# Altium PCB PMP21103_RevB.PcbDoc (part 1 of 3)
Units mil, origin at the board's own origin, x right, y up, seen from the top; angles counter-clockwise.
Board outline 3500 x 4000 mil, 4 copper layers (Top Layer, Signal Layer 1, Signal Layer 2, Bottom Layer), stack 61.2 mil thick; 194 components, 123 nets, 630 pads, 189 vias.
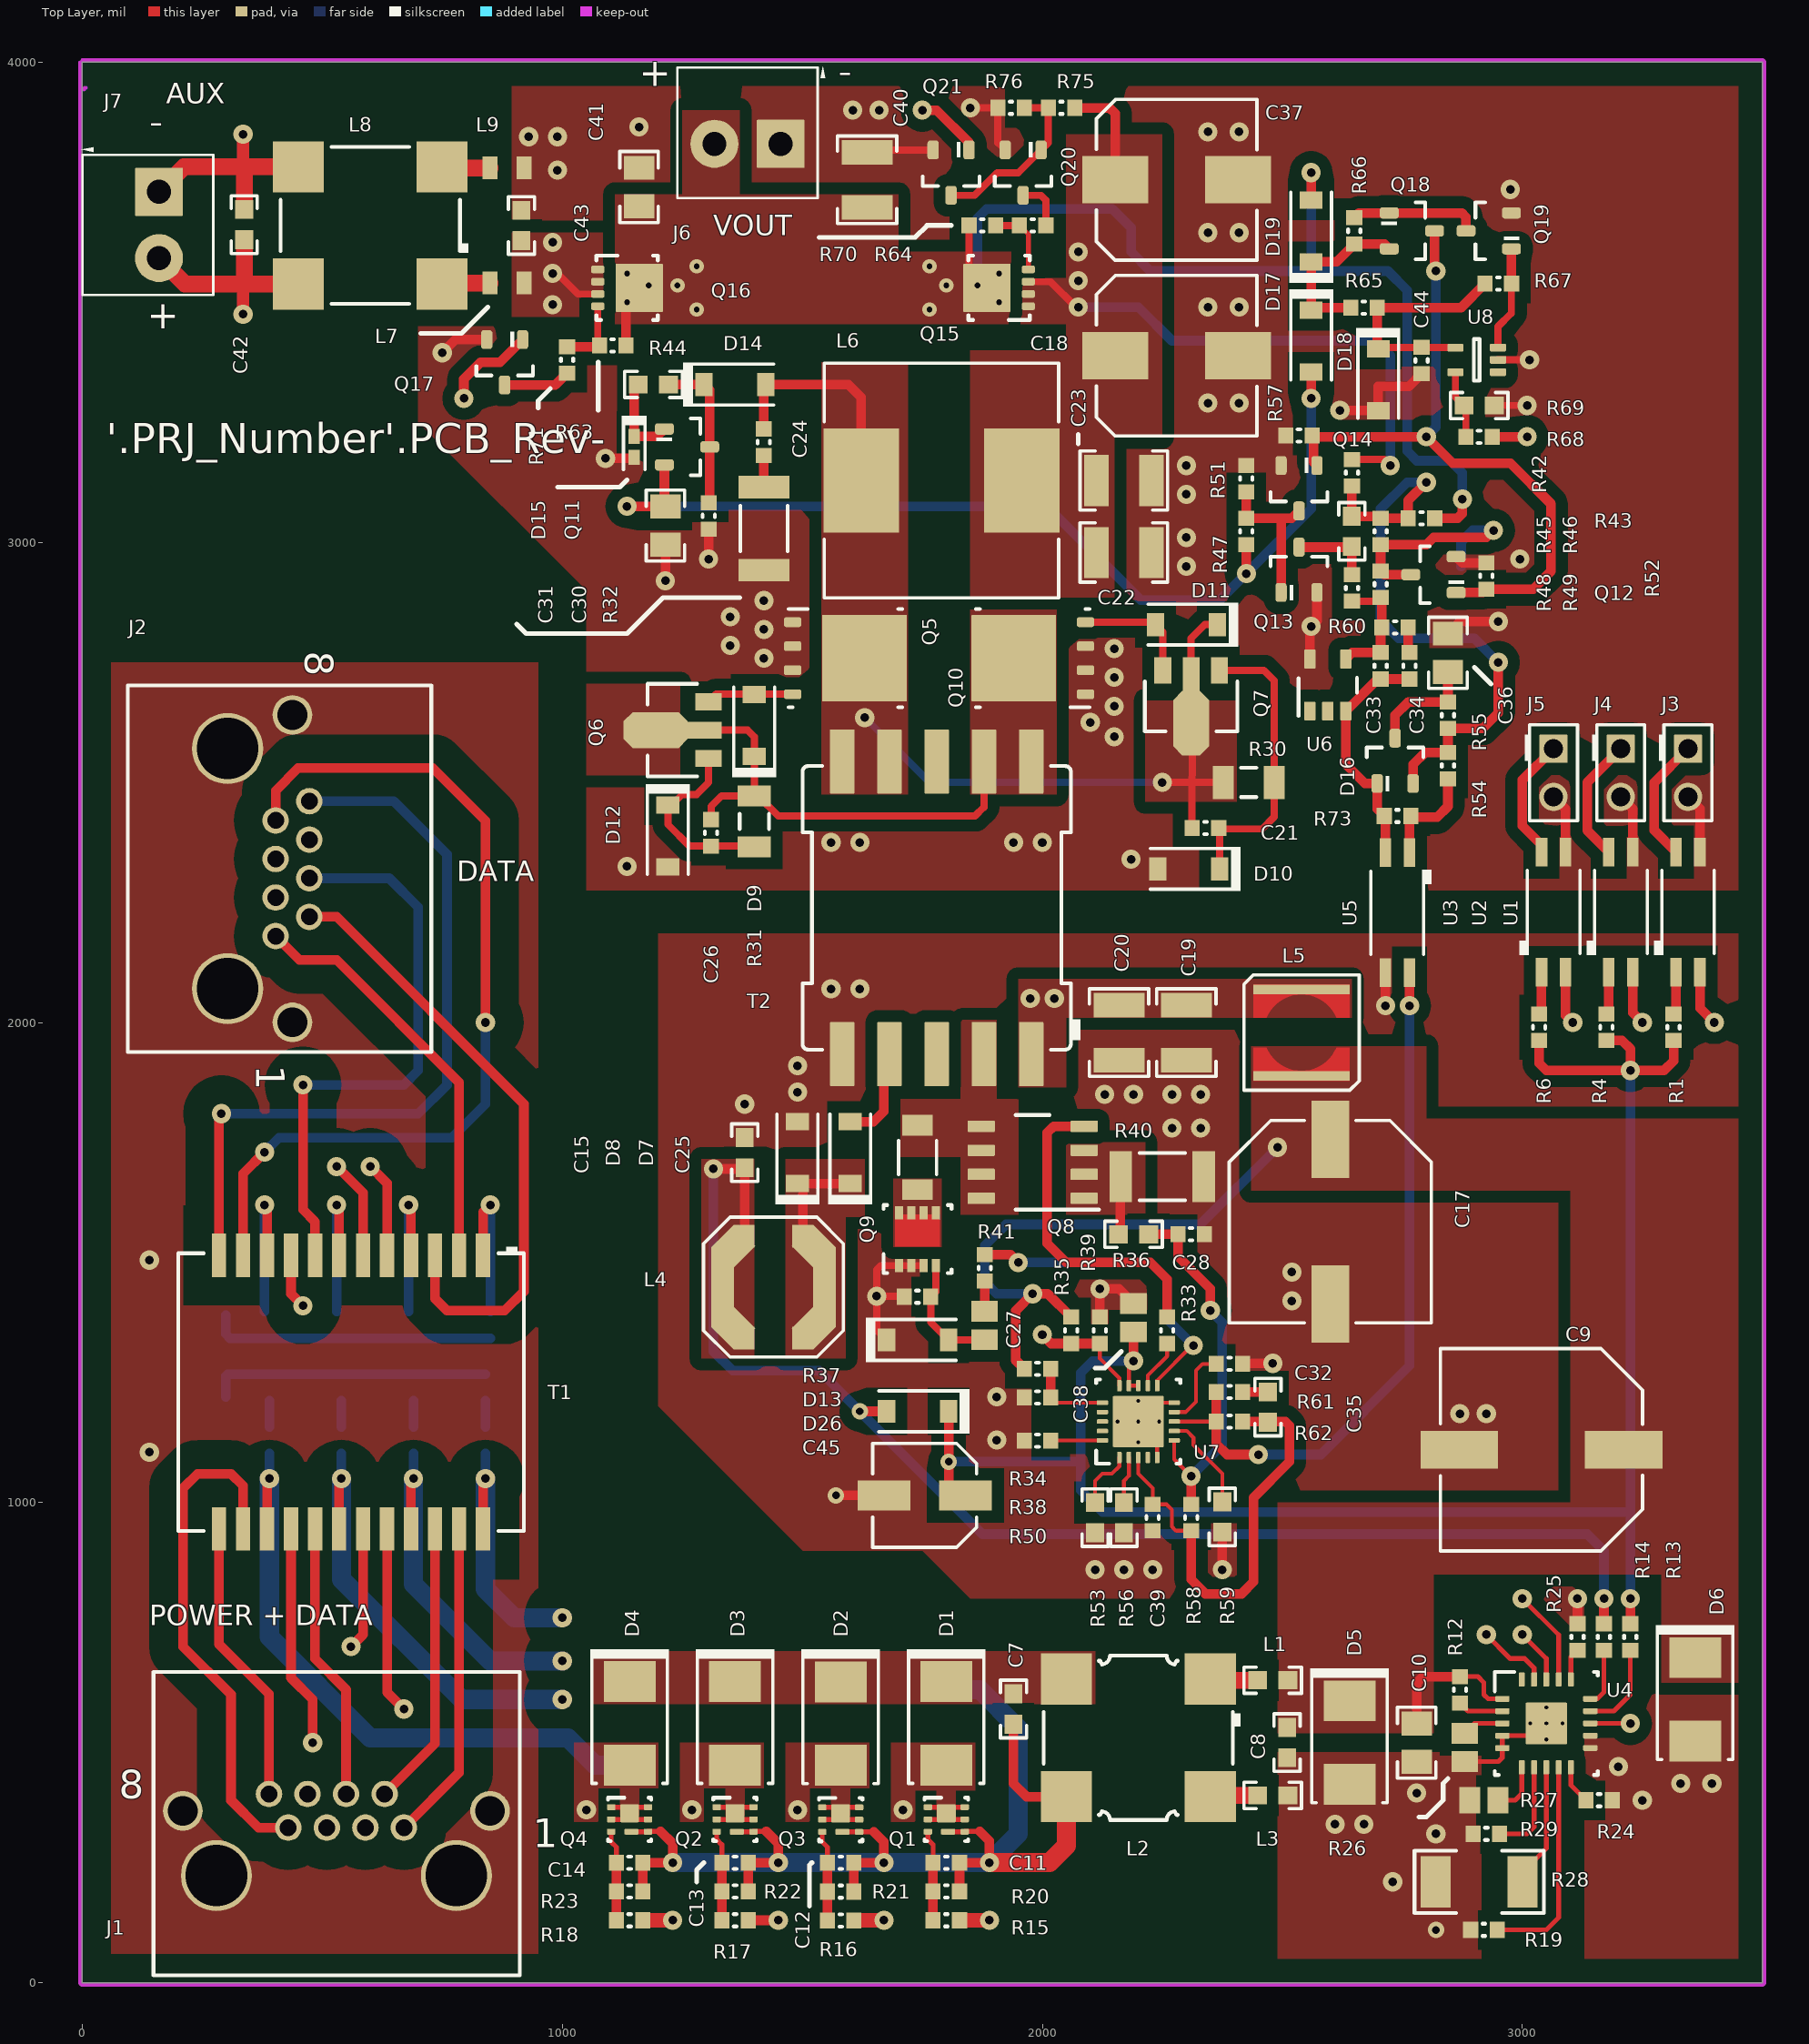
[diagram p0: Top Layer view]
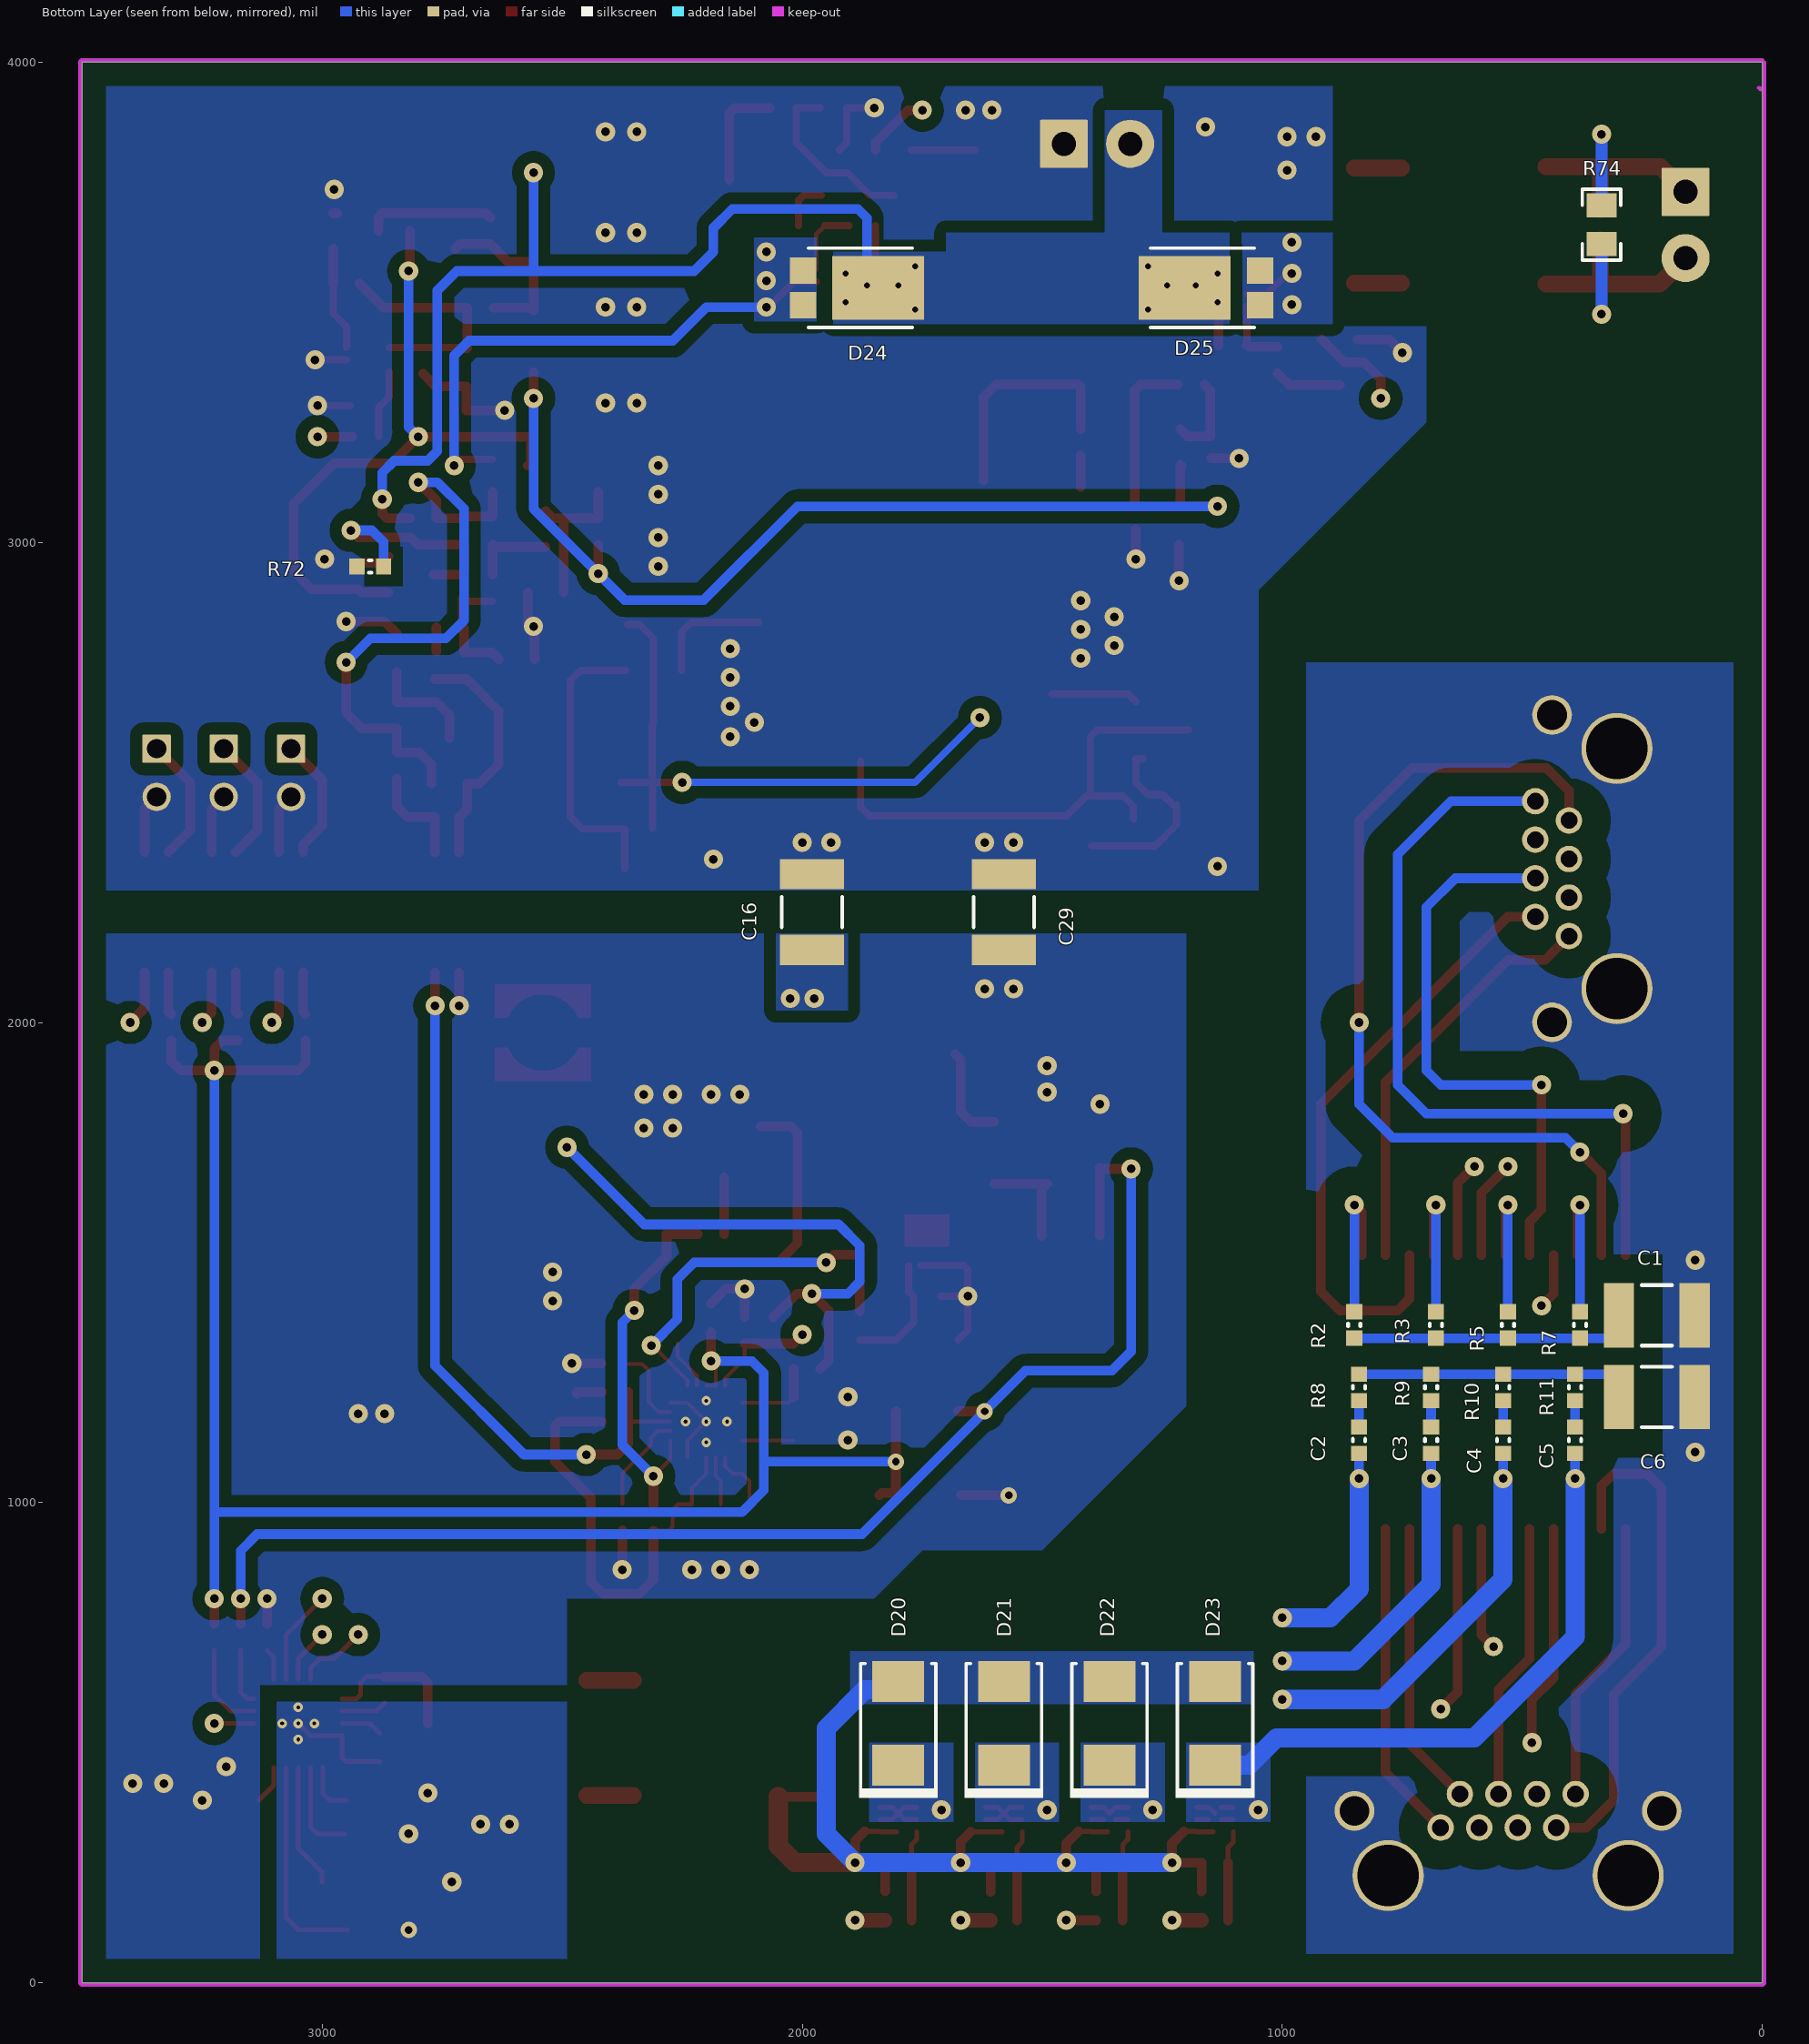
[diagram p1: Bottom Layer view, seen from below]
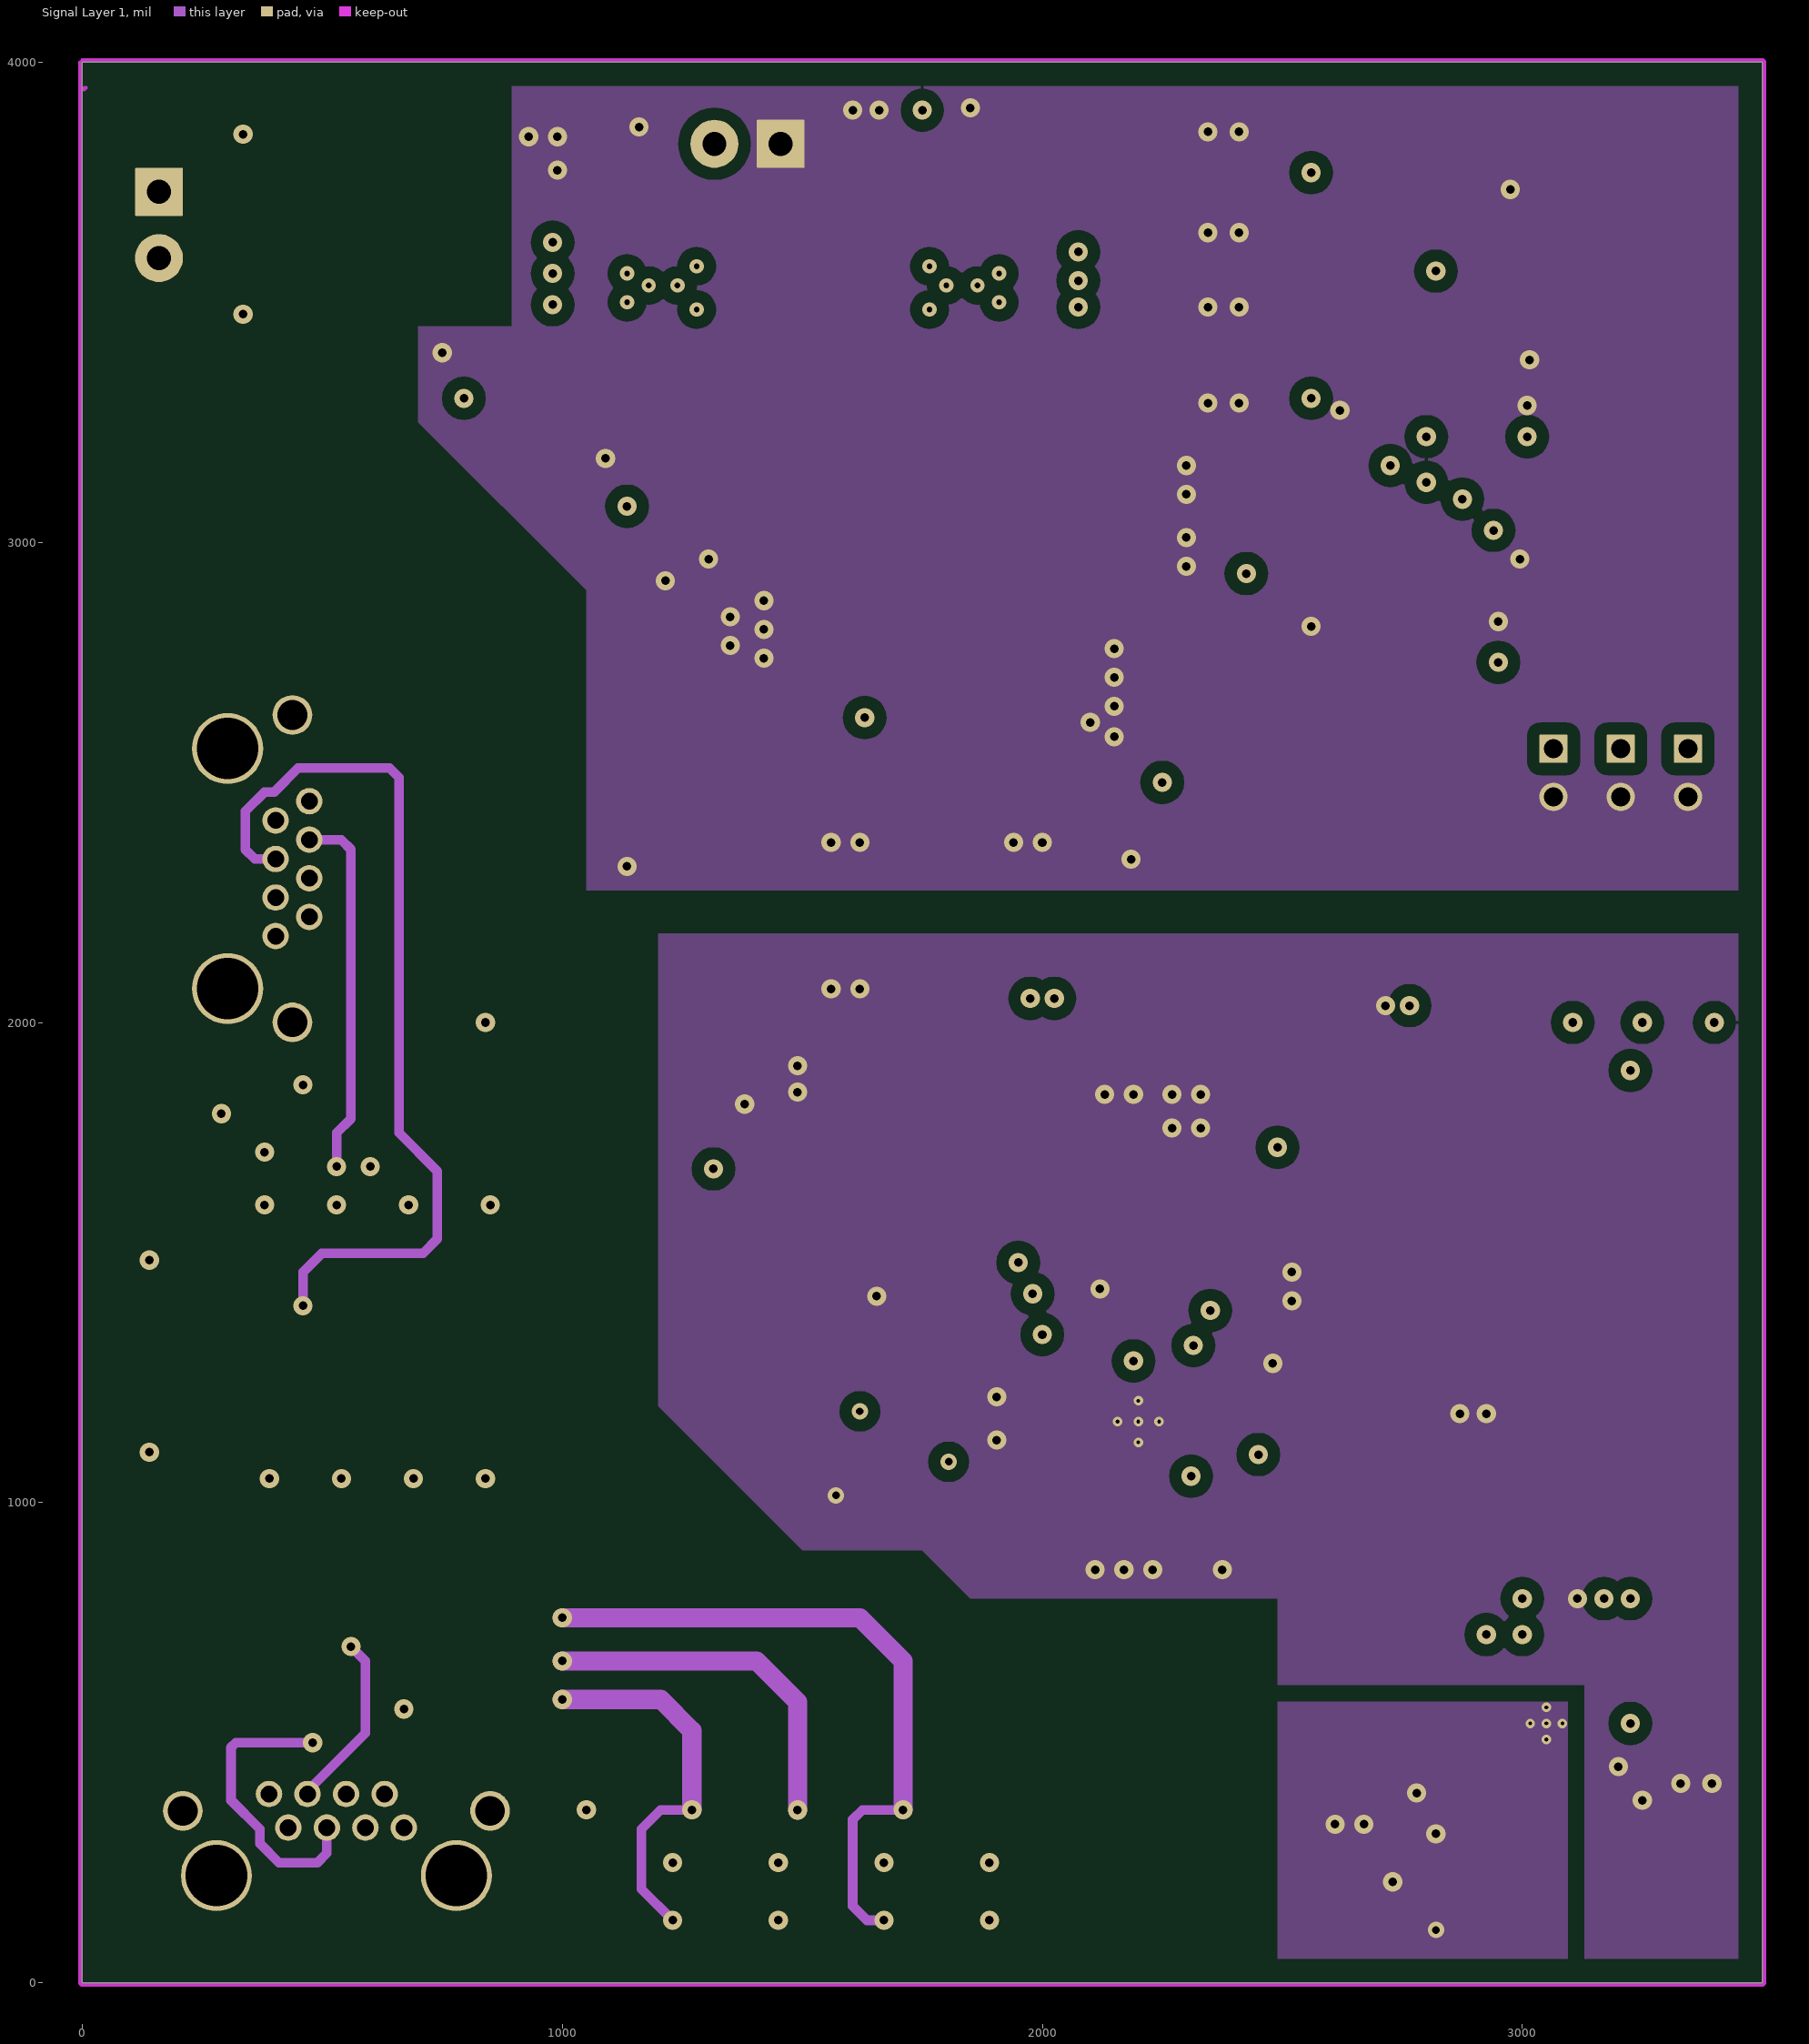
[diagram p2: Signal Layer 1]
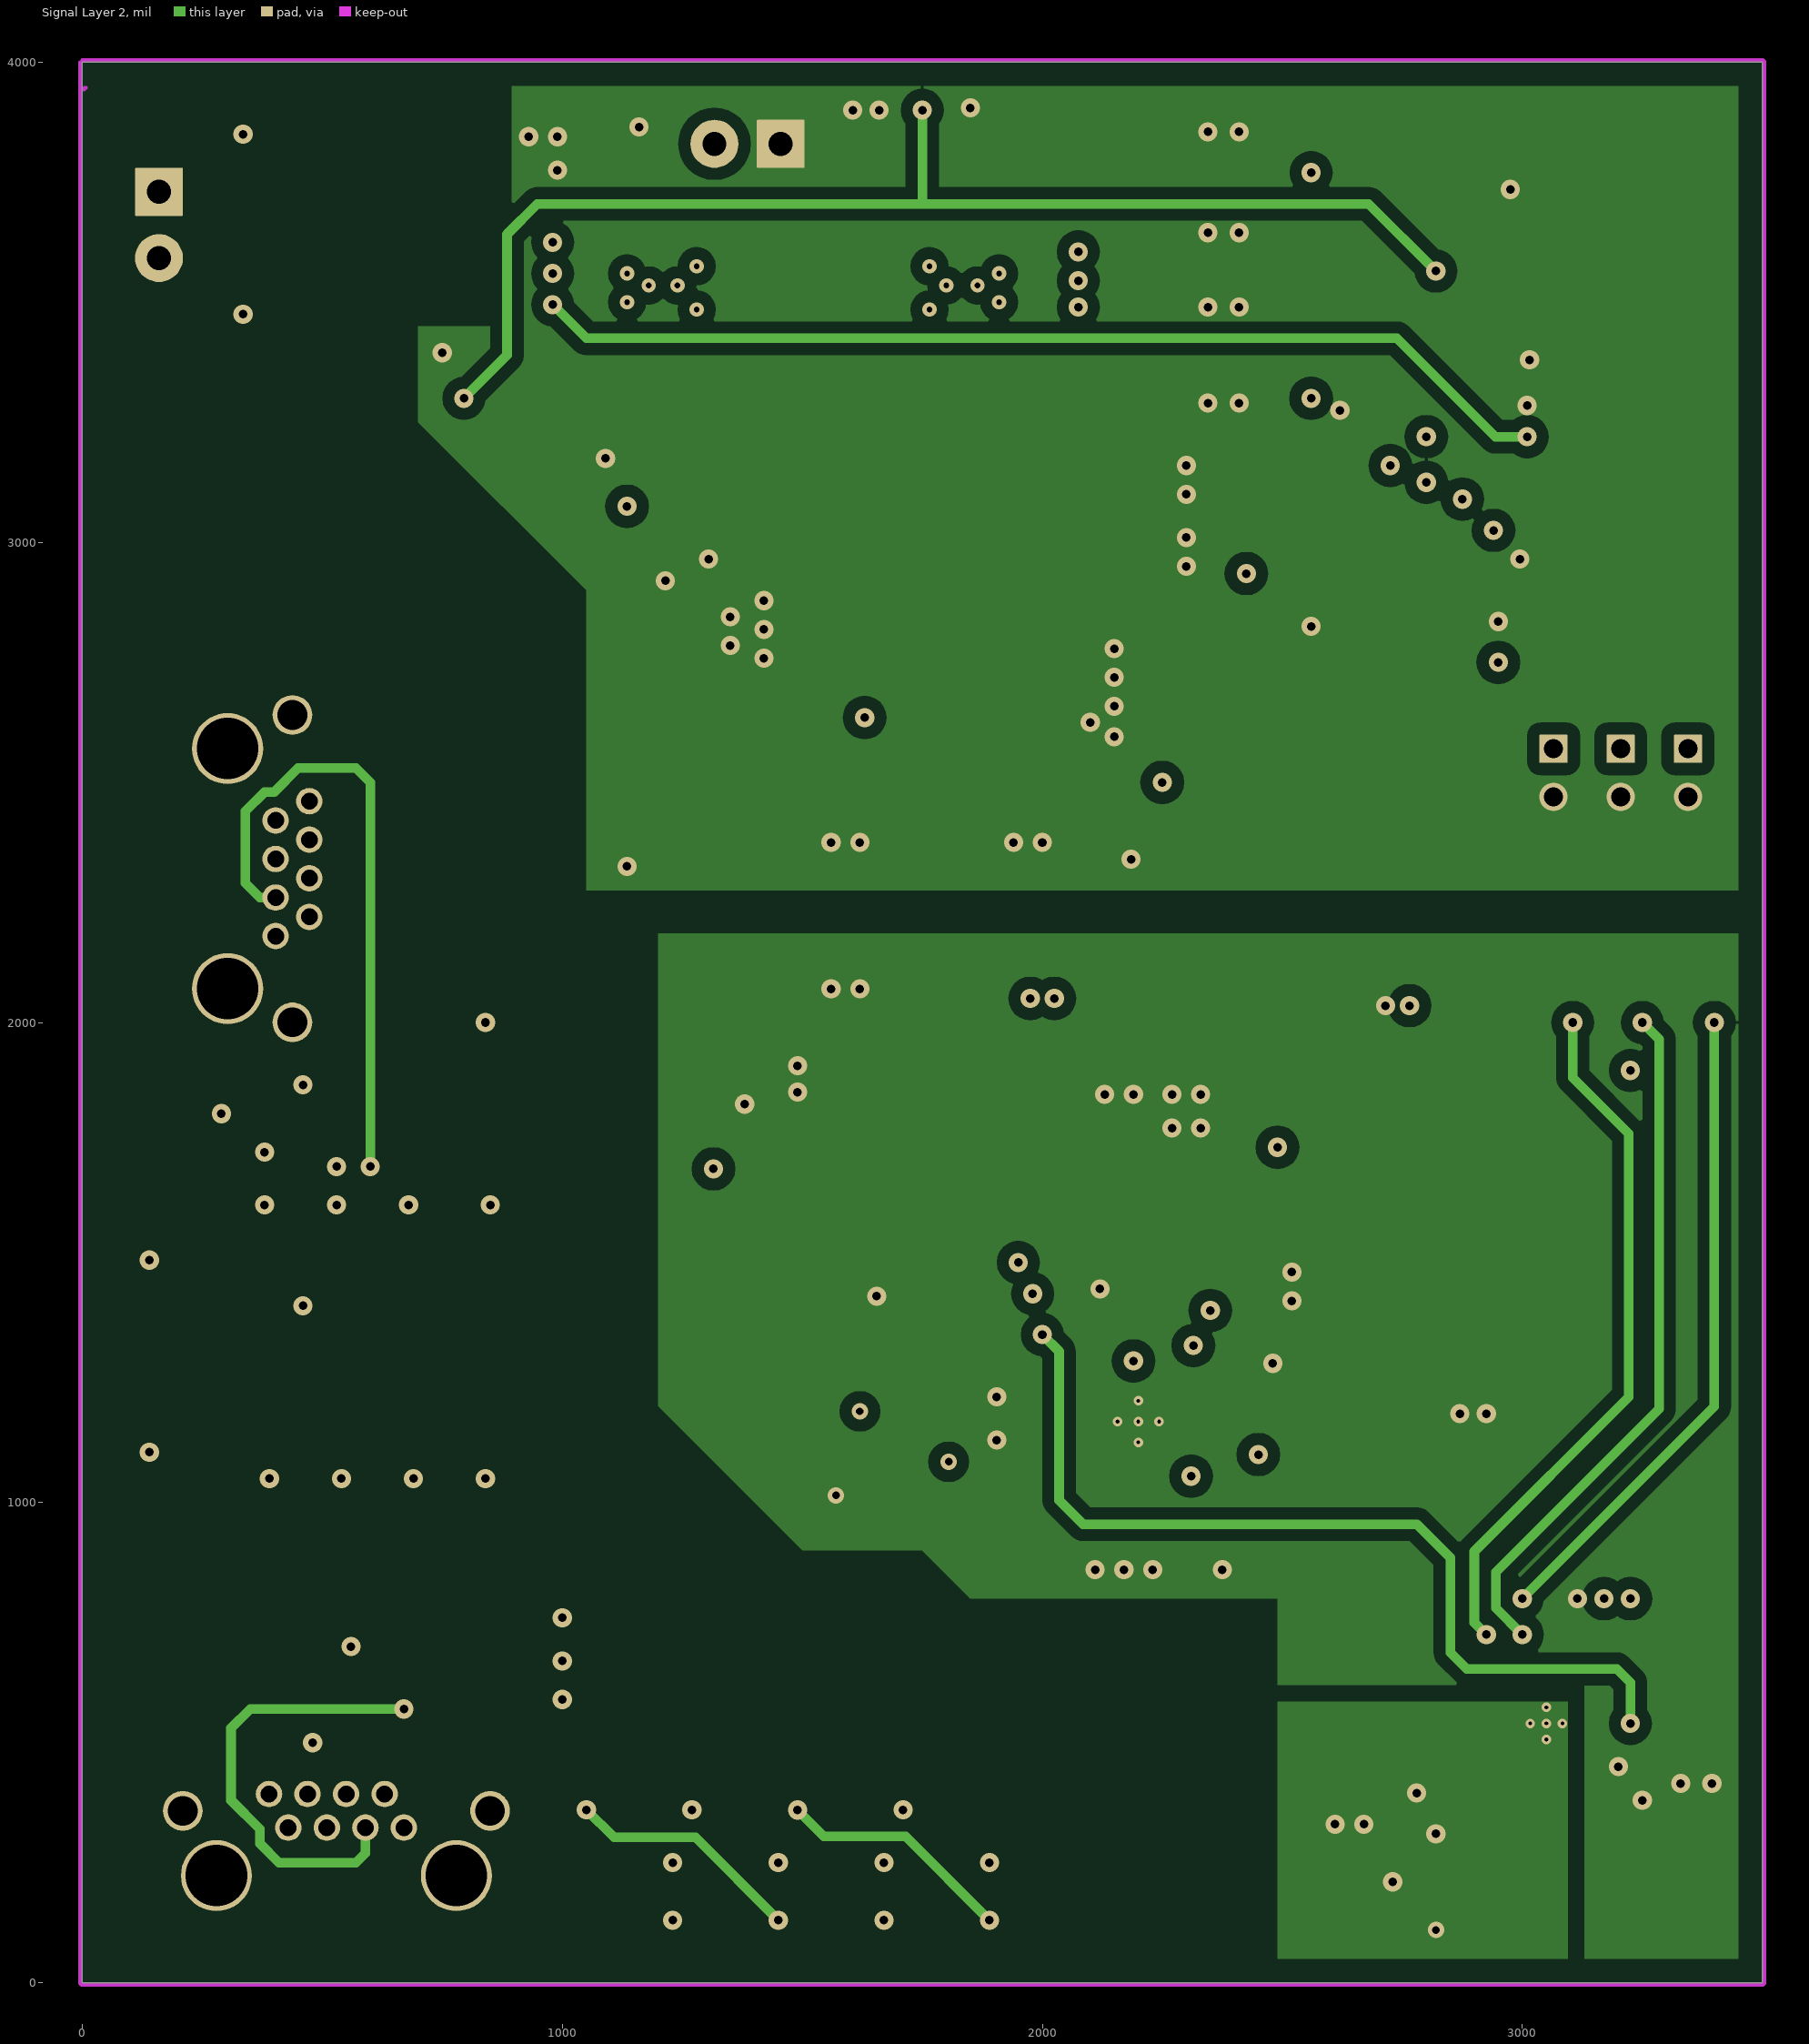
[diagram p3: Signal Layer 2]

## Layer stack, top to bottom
Top Solder: solder mask 0.4, Solder Resist, Dk 3.5
Top Layer: signal copper 2.8
Dielectric 2: core 20, Dk 4.2
Signal Layer 1: signal copper 2.8
Dielectric1: prepreg 10, FR-4, Dk 4.2
Signal Layer 2: signal copper 2.8
Dielectric 3: core 20, Dk 4.2
Bottom Layer: signal copper 2.8
Bottom Solder: solder mask 0.4, Solder Resist, Dk 3.5

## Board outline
0,0 3500,0 3500,4000 0,4000

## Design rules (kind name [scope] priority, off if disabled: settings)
AcuteAngle [All] p1: minimum=4.50000000000000E+0001 checktracksonly=FALSE
AssemblyTestPointUsage [All] p1: valid=2
BoardOutlineClearance BoardOutlineClearance_MountingHoles [OnCopper and InComponentClass('Mounting Holes')] p1: gap=40 ignorepadtopadclearanceinfootprint=FALSE
BoardOutlineClearance BoardOutlineClearance_Poly [OnCopper and IsPoly] p2: gap=25 ignorepadtopadclearanceinfootprint=FALSE
BoardOutlineClearance [OnCopper and Not InComponentClass('Logo') and not InComponentClass('FiducialMark') and not InRegion(1000,500,4000,800) and not InPoly] p3: gap=75 ignorepadtopadclearanceinfootprint=FALSE
Clearance Clearance_2 [InNamedPolygon('TOP_LAYER_BSVG_P132')] p1: gap=60 ignorepadtopadclearanceinfootprint=FALSE
Clearance Clearance_1 [InNamedPolygon('BOTTOM_LAYER_BSVG_P134')] p2: gap=60 ignorepadtopadclearanceinfootprint=FALSE
Clearance Clearance_Keepouts [((IsTrack Or IsArc) And Not InPoly) And IsFree and IsKeepOut vs ((IsTrack Or IsArc) And Not InPoly) And IsFree and IsKeepOut] p3: gap=0 ignorepadtopadclearanceinfootprint=FALSE
Clearance Clearance_Poly [InPolygon] p4: gap=25 ignorepadtopadclearanceinfootprint=FALSE except(0: Arc-Hole Track-Hole SMDPad-Hole THPad-Hole Via-Hole Fill-Hole Poly-Hole Region-Hole Text-Hole)
Clearance Clearance_FiducialMark [IsKeepOut and InComponentClass('FiducialMark') vs IsPad and InComponentClass('FiducialMark')] p5: gap=0 ignorepadtopadclearanceinfootprint=FALSE
Clearance [All] p6: gap=7.87 ignorepadtopadclearanceinfootprint=FALSE except(0: Arc-Hole Track-Hole SMDPad-Hole THPad-Hole Via-Hole Fill-Hole Poly-Hole Region-Hole Text-Hole)
ComponentClearance ComponentClearance_MountingHoles_FiducialMarks [InComponentClass('Mounting Holes') vs InComponentClass('FiducialMark')] p1: gap=50 collisioncheckmode=3 verticalgap=10 showdistances=FALSE
ComponentClearance ComponentClearance_Shunt [InComponentClass('Header') vs InComponentClass('Shunt')] p2: gap=0 collisioncheckmode=3 verticalgap=0 showdistances=FALSE
ComponentClearance ComponentClearance_Logo [InComponentClass('Logo')] p3: gap=50 collisioncheckmode=3 verticalgap=10 showdistances=FALSE
ComponentClearance ComponentClearance_ScrewToNut [(HasFootprint('NY PMS 440 0025 PH')) vs (HasFootprint('Keystone_1902C'))] p4: gap=5 collisioncheckmode=3 verticalgap=10 showdistances=FALSE
ComponentClearance ComponentClearance_MountingHoles [InComponentClass('Mounting Holes')] p5: gap=250 collisioncheckmode=3 verticalgap=100000 showdistances=FALSE
ComponentClearance ComponentClearance_SmallPassives [HasFootprint('0201*') or HasFootprint('0402*') or HasFootprint('0508') or HasFootprint('0603*') or HasFootprint('0612') or HasFootprint('0805*') or HasFootprint('0815*') or HasFootprint('0830*') or HasFootprint('1206*') or HasFootprint('1210*') or HasFootprint('1808*') or HasFootprint('1812*') or HasFootprint('1825*') or HasFootprint('2010*') or HasFootprint('2220*') or HasFootprint('2225*') or HasFootprint('2512*') or HasFootprint('2728*') or HasFootprint('3518*') vs HasFootprint('0201*') or HasFootprint('0402*') or HasFootprint('0508') or HasFootprint('0603*') or HasFootprint('0612') or HasFootprint('0805*') or HasFootprint('0815*') or HasFootprint('0830*') or HasFootprint('1206*') or HasFootprint('1210*') or HasFootprint('1808*') or HasFootprint('1812*') or HasFootprint('1825*') or HasFootprint('2010*') or HasFootprint('2220*') or HasFootprint('2225*') or HasFootprint('2512*') or HasFootprint('2728*') or HasFootprint('3518*')] p6: gap=14.96 collisioncheckmode=3 verticalgap=10 showdistances=FALSE
ComponentClearance ComponentClearance_THtoSMT [IsThruComponent vs IsSMTComponent] p7: gap=40 collisioncheckmode=3 verticalgap=30 showdistances=FALSE
ComponentClearance ComponentClearance_THtoTH [IsThruComponent vs IsThruComponent] p8: gap=30 collisioncheckmode=3 verticalgap=30 showdistances=FALSE
ComponentClearance [All] p9: gap=30 collisioncheckmode=3 verticalgap=10 showdistances=FALSE
DiffPairsRouting [All] p1: maxlimit=100 minlimit=10 mostfreqgap=10 toplayer_minwidth=15 toplayer_maxwidth=15 toplayer_prefwidth=15 midlayer1_minwidth=15 midlayer1_maxwidth=15 midlayer1_prefwidth=15 midlayer2_minwidth=15 midlayer2_maxwidth=15 midlayer2_prefwidth=15 bottomlayer_minwidth=15 bottomlayer_maxwidth=15 bottomlayer_prefwidth=15 maxuncoupledlength=1000
FabricationTestPointUsage TestPointUsage [All] p1: valid=2 allowmultiple=FALSE
FabricationTestpoint Testpoint [All] p1: side=3 testpointundercomponent=TRUE minsize=40 maxsize=100 preferedsize=60 minholesize=0 maxholesize=40 preferedholesize=32 testpointgrid=1 allowsidetop=TRUE allowsidebottom=TRUE usegrid=TRUE gridtolerance=0.01
FanoutControl Fanout_LCC [IsLCC] p1: bgadir=Out bgaviamode=Centered fanoutstyle=Auto fanoutdirection=Alternating viagrid=1 // Fanout_LCC (Default Rule)
FanoutControl Fanout_BGA [IsBGA] p2: bgadir=Out bgaviamode=Centered fanoutstyle=Auto fanoutdirection=Alternating viagrid=1 // Fanout_BGA (Default Rule)
FanoutControl Fanout_Default [All] p4: bgadir=Out bgaviamode=Centered fanoutstyle=Auto fanoutdirection=Alternating viagrid=1 // Fanout_Default (Default Rule)
FanoutControl Fanout_Small [(CompPinCount < 5)] p5: bgadir=Out bgaviamode=Centered fanoutstyle=Auto fanoutdirection=OutThenIn viagrid=1 // Fanout_Small (Default Rule)
HoleSize [All] p1: absolutevalues=TRUE maxlimit=251 minlimit=7.87 maxpercent=80.000 minpercent=20.000
MinimumAnnularRing MinimumAnnularRing_ThermalPadVias [IsVia and InAnyComponent] p1: minimumring=5.91
MinimumAnnularRing [All] p2: minimumring=8
MinimumSolderMaskSliver MinimumSolderMaskSliver_Logo [InComponentClass('Logo') vs InComponentClass('Logo')] p1: minsoldermaskwidth=0.7
MinimumSolderMaskSliver [All] p2: minsoldermaskwidth=3.94
PlaneConnect [All] p1: planeconnectstyle=Relief reliefexpansion=10 reliefentries=4 reliefconductorwidth=10 reliefairgap=10
PolygonConnect [All] p1: connectstyle=Direct reliefconductorwidth=10 reliefentries=4 polygonreliefangle="90 Angle" airgapwidth=10
RoutingVias ThermalPadVias [IsVia and InAnyComponent] p1: holewidth=7.87 width=19.68 viastyle="Through Hole" minholewidth=7.87 minwidth=19.68 maxholewidth=12.99 maxwidth=23.62
RoutingVias [All] p2: holewidth=18 width=40 viastyle="Through Hole" minholewidth=7.87 minwidth=26 maxholewidth=40 maxwidth=65
SilkToBoardRegionClearance [Not ((IsComment or IsDesignator) And (Hide <> 'False')) and not InRegion(1000,500,4000,800)] p1:
SilkToSilkClearance SilkToSilkClearance_Pb-FreeLogo [(HasFootprint('Pb-Free_Overlay_Medium') OR HasFootprint('Pb-Free_Overlay_Small')) vs (HasFootprint('Pb-Free_Overlay_Medium') OR HasFootprint('Pb-Free_Overlay_Small'))] p1: silktosilkclearance=0
SilkToSilkClearance [All] p2: silktosilkclearance=4
SilkToSolderMaskClearance SilkToComponentPadClearance [(IsPad or IsFill or IsRegion) and InAnycomponent] p1: minsilkscreentomaskgap=5 clearancetoexposedcopper=TRUE
SilkToSolderMaskClearance "Silk to Solder Mask Opening" [All] p2: minsilkscreentomaskgap=4 clearancetoexposedcopper=FALSE
SolderMaskExpansion [All] p1: expansion=1.97
Width [All] p1: maxlimit=100 minlimit=6 preferedwidth=10 checkconnectedcopper=TRUE
15 further rules are at their usual default settings.

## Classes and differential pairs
component class Header: J3 J4 J5
component class PMP21103_RevB_SH1: C1 C2 C3 C4 C5 C6 C7 C8 C9 C10 C11 C12 C13 C14 D1 D2 D3 D4 D5 D6 D20 D21 D22 D23 D26 J1 J2 J3 J4 J5 L1 L2 L3 Q1 Q2 Q3 Q4 R1 R2 R3 R4 R5 R6 R7 R8 R9 R10 R11 R12 R13 R14 R15 R16 R17 R18 R19 R20 R21 R22 R23 R24 R25 R26 R27 R28 R29 T1 U1 U2 U3 U4
component class PMP21103_RevB_SH2: C15 C16 C17 C18 C19 C20 C21 C22 C23 C24 C25 C26 C27 C28 C29 C30 C31 C32 C33 C34 C35 C36 C37 C38 C39 C45 D7 D8 D9 D10 D11 D12 D13 D14 D15 D16 L4 L5 L6 Q5 Q6 Q7 Q8 Q9 Q10 Q11 Q12 Q13 Q14 R30 R31 R32 R33 R34 R35 R36 R37 R38 R39 R40 R41 R42 R43 R44 R45 R46 R47 R48 R49 R50 R51 R52 R53 R54 R55 R56 R57 R58 R59 R60 R61 R62 R72 R73 T2 U5 U6 U7
component class PMP21103_RevB_SH3: C40 C41 C42 C43 C44 D17 D18 D19 D24 D25 J6 J7 L7 L8 L9 Q15 Q16 Q17 Q18 Q19 Q20 Q21 R63 R64 R65 R66 R67 R68 R69 R70 R71 R74 R75 R76 U8

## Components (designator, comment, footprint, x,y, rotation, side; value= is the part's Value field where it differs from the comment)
C1 "GR443QR73D102KW01L" 1812 220,1390 r0 bottom value=1000pF
C2 "GRM188R72A103KA01D" 0603L 840,1130 r90 bottom value=0.01uF
C3 "GRM188R72A103KA01D" 0603L 690,1130 r90 bottom value=0.01uF
C4 "GRM188R72A103KA01D" 0603L 540,1130 r90 bottom value=0.01uF
C5 "GRM188R72A103KA01D" 0603L 390,1130 r90 bottom value=0.01uF
C6 "GR443QR73D102KW01L" 1812 220,1220 r180 bottom value=1000pF
C7 "GRM188R72A102KA01D" 0603 1940,570 r270 top value=1000pF
C8 "GRM188R72A102KA01D" 0603 2510,500 r270 top value=1000pF
C9 "EEE-FK1K470P" SM_RADIAL_G 3040,1110 r180 top value=47uF
C10 "C2012X7R2A104K125AA" 0805_HV 2780,500 r90 top value=0.1uF
C11 "GRM1885C1H331JA01D" 0603L 1800,250 r0 top value=330pF
C12 "GRM1885C1H331JA01D" 0603L 1580,249.69 r0 top value=330pF
C13 "GRM1885C1H331JA01D" 0603L 1360,250 r0 top value=330pF
C14 "GRM1885C1H331JA01D" 0603L 1140.32,250 r0 top value=330pF
C15 "C1608X7R1H104K080AA" 0603 1380,1728.74 r270 top value=0.1uF
C16 "C4532X7R3D222K130KA" 1812 1980,2230 r270 bottom value=2200pF
C17 "EEE-FK1K470P" SM_RADIAL_G 2600,1585 r270 top value=47uF
C18 "20SVP47M" SM_RADIAL_8MM 2280,3388.74 r0 top value=47uF
C19 "GRM32ER72A225KA35L" 1210_270 2300,1978.74 r270 top value=2.2uF
C20 "GRM32ER72A225KA35L" 1210_270 2160,1978.74 r270 top value=2.2uF
C21 "C1608C0G1H101J080AE" 0603L 2340,2405 r180 top value=100pF
C22 "885012209028" 1210_220 2170,2978.74 r0 top value=10uF
C23 "885012209028" 1210_220 2170,3128.74 r0 top value=10uF
C24 "GRM188R71H222KA01D" 0603L 1420,3208.74 r270 top value=2200pF
C25 "GRM31CR72E473KW03L" 1206_180 1740,1718.74 r270 top value=0.047uF
C26 "C1608C0G1H101J080AE" 0603L 1310,2395 r270 top value=100pF
C27 "GRM21BR71E105KA99L" 0805L 1880,1368.74 r90 top value=1uF
C28 "GRM1885C1H470JA01D" 0603L 2310,1558.74 r0 top value=47pF
C29 "C4532X7R3D222K130KA" 1812 1580,2230 r270 bottom value=2200pF
C30 "C1608X7R1H104K080AA" 0603L 1305,3055 r90 top value=0.1uF
C31 "GRM21BR71E105KA99L" 0805_HV 1215,3035 r270 top value=1uF
C32 "GRM188R71H223KA01D" 0603L 2390,1288.74 r0 top value=0.022uF
C33 "C1608C0G1H101J080AE" 0603L 2704.8,2742.77 r270 top value=100pF
C34 "GRM188R71H223KA01D" 0603L 2764.8,2742.77 r270 top value=0.022uF
C35 "GRM188R71H102KA01D" 0603 2470,1198.74 r270 top value=1000pF
C36 "GRM21BR71E105KA99L" 0805_HV 2845,2770 r90 top value=1uF
C37 "20SVP47M" SM_RADIAL_8MM 2280,3755 r0 top value=47uF
C38 "GRM21BR71E105KA99L" 0805L 2190,1385 r90 top value=1uF
C39 "C1608X7R1H104K080AA" 0603L 2230,968.74 r90 top value=0.1uF
C40 "885012209028" 1210_220 1635,3755 r90 top value=10uF
C41 "GRM21BR71E105KA99L" 0805_HV 1160,3740 r90 top value=1uF
C42 "GRM188R72A102KA01D" 0603 337.51,3661.67 r90 top value=1000pF
C43 "GRM188R72A102KA01D" 0603 915,3660 r90 top value=1000pF
C44 "C1608X7R1H103K080AA" 0603L 2790,3378.74 r90 top value=0.01uF
C45 "EEE-FK1E220R" SM_RADIAL_C 1755,1015 r180 top value=22uF
D1 "B2100-13-F" SMB 1800,540 r270 top value=100V
D2 "B2100-13-F" SMB 1580,539.69 r270 top value=100V
D3 "B2100-13-F" SMB 1360,540 r270 top value=100V
D4 "B2100-13-F" SMB 1140.32,540 r270 top value=100V
D5 "SMBJ58A-13-F" SMB 2640,500 r270 top value=58V
D6 "SMBJ58A-13-F" SMB 3360,590 r270 top value=58V
D7 "MMSD4148T1G" SOD-123 1600,1728.74 r90 top value=100V
D8 "MMSD4148T1G" SOD-123 1490,1728.74 r90 top value=100V
D9 "MMSD4148T1G" SOD-123 1400,2618.74 r90 top value=100V
D10 "MMSZ5240B-7-F" SOD-123 2305,2320 r180 top value=10V
D11 "MMSD4148T1G" SOD-123 2300,2828.74 r180 top value=100V
D12 "MMSZ5240B-7-F" SOD-123 1220,2388.74 r270 top value=10V
D13 "MMSD4148T1G" SOD-123 1740,1338.74 r0 top value=100V
D14 "MMSD4148T1G" SOD-123 1360,3328.74 r0 top value=100V
D15 "BZT52C9V1T-7" SOD-523 1150,3198.74 r270 top value=9.1V
D16 "BAT54S-7-F" SOT-23 2735,2545 r90 top value=30V
D17 "MMSD4148T1G" SOD-123 2560,3418.74 r270 top value=100V
D18 "MMSZ5231B-7-F" SOD-123 2700,3338.74 r270 top value=5.1V
D19 "MMSD4148T1G" SOD-123 2560,3648.74 r90 top value=100V
D20 "B2100-13-F" SMB 1800,540 r90 bottom value=100V
D21 "B2100-13-F" SMB 1580,540 r90 bottom value=100V
D22 "B2100-13-F" SMB 1360,540 r90 bottom value=100V
D23 "B2100-13-F" SMB 1140,540 r90 bottom value=100V
D24 "PDS835L-13" POWERDI5 1920,3530 r180 bottom value=35V
D25 "PDS835L-13" POWERDI5 1125,3530 r0 bottom value=35V
D26 "MMSD4148T1G" SOD-123 1740,1190 r180 top value=100V
J1 "1-406541-1" TEC_1-406541-1 530,330 r0 top
J2 "1-406541-1" TEC_1-406541-1 410,2320 r270 top
J3 "PEC02SAAN" CONN_PEC02SAAN 3345,2520 r270 top
J4 "PEC02SAAN" CONN_PEC02SAAN 3205,2520 r270 top
J5 "PEC02SAAN" CONN_PEC02SAAN 3065,2520 r270 top
J6 "ED555/2DS" TERM_BLK_ED555-2DS 1455,3830 r180 top
J7 "ED555/2DS" TERM_BLK_ED555-2DS 160,3730 r270 top
L1 "MPZ1608S221A" 0603 2480,630 r0 top value="220 ohm"
L2 "744272251" WE-SL5 2200,510 r270 top value=250uH
L3 "MPZ1608S221A" 0603 2480,390 r0 top value="220 ohm"
L4 "LPS6235-155MLB" LPS6235 1440,1448.74 r0 top value=1.5mH
L5 "MSS5131-332MLB" MSS5131 2540,1978.74 r90 top value=3.3uH
L6 "MSS1278-223MLB" MSS1278 1790,3128.74 r0 top value=22uH
L7 "MPZ2012S300AT000" MPZ2012 885,3540 r180 top value="30 ohm"
L8 "744273801" WE-SL5_HC 600,3660 r180 top value=9uH
L9 "MPZ2012S300AT000" MPZ2012 885,3780 r180 top value="30 ohm"
Q1 "CSD19538Q2" DQK0006C 1800,340 r0 top value=100V
Q2 "CSD19538Q2" DQK0006C 1360,340 r0 top value=100V
Q3 "CSD19538Q2" DQK0006C 1580,339.69 r0 top value=100V
Q4 "CSD19538Q2" DQK0006C 1140.32,340 r0 top value=100V
Q5 "CSD18534Q5A" DQJ0008A 1590,2758.74 r0 top value=60V
Q6 "FCX493TA" SOT-89-3 1230,2608.74 r180 top value="100 V"
Q7 "FCX493TA" SOT-89-3 2310,2658.74 r270 top value="100 V"
Q8 "FDS86242" SOIC-8 1980,1708.74 r180 top value=150V
Q9 "FDMC2523P" MLP08S 1740,1548.74 r90 top value=-150V
Q10 "CSD18534Q5A" DQJ0008A 1980,2758.74 r180 top value=60V
Q11 "MMBT3904-7-F" SOT-23 1260,3198.74 r0 top value="40 V"
Q12 "2N7002P,215" SOT-23 2814.8,2932.77 r180 top value=60V
Q13 "2N7002P,215" SOT-23 2534.8,2942.77 r90 top value=60V
Q14 "2N7002P,215" SOT-23 2534.8,3112.77 r270 top value=60V
Q15 "CSD25402Q3A" DNH0008A_NV 1910,3530 r180 top value=-20V
Q16 "CSD25402Q3A" DNH0008A_NV 1135,3530 r0 top value=-20V
Q17 "2N7002P,215" SOT-23 880,3375 r270 top value=60V
Q18 "BSH201,215" SOT-23 2770,3648.74 r0 top value=-60V
Q19 "BSS123" SOT-23 2930,3648.74 r180 top value=100V
Q20 "2N7002P,215" SOT-23 1960,3770 r270 top value=60V
Q21 "2N7002P,215" SOT-23 1810,3770 r270 top value=60V
R1 "CRCW060310K0FKEA" 0603L 3315,1990 r90 top value=10.0k
R2 "CRCW060375R0FKEA" 0603L 850,1370 r90 bottom value=75.0
R3 "CRCW060375R0FKEA" 0603L 680,1370 r90 bottom value=75.0
R4 "CRCW060310K0FKEA" 0603L 3175,1990 r90 top value=10.0k
R5 "CRCW060375R0FKEA" 0603L 530,1370 r90 bottom value=75.0
R6 "CRCW060310K0FKEA" 0603L 3035,1990 r90 top value=10.0k
R7 "CRCW060375R0FKEA" 0603L 380,1370 r90 bottom value=75.0
R8 "CRCW060375R0FKEA" 0603L 840,1240 r270 bottom value=75.0
R9 "CRCW060375R0FKEA" 0603L 690,1240 r270 bottom value=75.0
R10 "CRCW060375R0FKEA" 0603L 540,1240 r270 bottom value=75.0
R11 "CRCW060375R0FKEA" 0603L 390,1240 r270 bottom value=75.0
R12 "CRCW060327K4FKEA" 0603L 2870,610 r90 top value=27.4k
R13 "CRCW06030000Z0EA" 0603L 3225,720 r90 top value=0
R14 "CRCW06030000Z0EA" 0603L 3170,720 r90 top value=0
R15 "CRCW06031M00FKEA" 0603L 1800,130 r180 top value=1.00Meg
R16 "CRCW06031M00FKEA" 0603L 1580,129.69 r180 top value=1.00Meg
R17 "CRCW06031M00FKEA" 0603L 1360,130 r180 top value=1.00Meg
R18 "CRCW06031M00FKEA" 0603L 1140.32,130 r180 top value=1.00Meg
R19 "CRCW060353K6FKEA" 0603L 2920,110 r180 top value=53.6k
R20 "CRCW0603232KFKEA" 0603L 1800,190 r180 top value=232k
R21 "CRCW0603232KFKEA" 0603L 1580,189.69 r180 top value=232k
R22 "CRCW0603232KFKEA" 0603L 1360,190 r180 top value=232k
R23 "CRCW0603232KFKEA" 0603L 1140.32,190 r180 top value=232k
R24 "CRCW06030000Z0EA" 0603L 3160,380 r180 top value=0
R25 "CRCW06030000Z0EA" 0603L 3115,720 r90 top value=0
R26 "CRCW080563R4FKEA" 0805L 2880,490 r90 top value=63.4
R27 "CRCW08051K21FKEA" 0805L 2920,380 r0 top value=1.21k
R28 "CRCW20101K30JNEF" 2010 2910,210 r0 top value=1.3k
R29 "CRCW060349K9FKEA" 0603L 2925,310 r0 top value=49.9k
R30 "CRCW12062K00JNEA" 1206L 2430,2500 r180 top value=2.0k
R31 "CRCW12062K00JNEA" 1206L 1400,2418.74 r270 top value=2.0k
R32 "CRCW201010R0JNEF" 2010L 1420,3028.74 r90 top value=10
R33 "CRCW06034R70JNEA" 0603L 2260,1358.74 r90 top value=4.7
R34 "CRCW0603121KFKEA" 0603L 1990,1278.74 r180 top value=121k
R35 "CRCW0603121KFKEA" 0603L 2060,1358.74 r90 top value=121k
R36 "CRCW06031K00FKEA" 0603 2190,1558.74 r180 top value=1.00k
R37 "CRCW060310K0FKEA" 0603L 1740,1428.74 r0 top value=10.0k
R38 "CRCW06030000Z0EA" 0603L 1990,1218.74 r0 top value=0
R39 "CRCW06034K22FKEA" 0603L 2120,1358.74 r270 top value=4.22k
R40 "ERJ-L1DKF10CU" 2010L 2250,1678.74 r180 top value=0.1
R41 "CRCW06034R70JNEA" 0603L 1880,1488.74 r270 top value=4.7
R42 "CRCW06030000Z0EA" 0603L 2645,3145 r90 top value=0
R43 "CRCW06030000Z0EA" 0603L 2790,3050 r0 top value=0
R44 "CRCW060315K0FKEA" 0603 1190,3328.74 r0 top value=15.0k
R45 "CRCW060321K5FKEA" 0603 2644.8,3022.77 r90 top value=21.5k
R46 "CRCW060328K7FKEA" 0603L 2704.8,3022.77 r90 top value=28.7k
R47 "CRCW06034K99FKEA" 0603L 2424.8,3022.77 r270 top value=4.99k
R48 "CRCW060310K0FKEA" 0603L 2645,2905 r90 top value=10.0k
R49 "CRCW060310K0FKEA" 0603L 2704.8,2912.77 r90 top value=10.0k
R50 "CRCW06035K90FKEA" 0603L 1990,1128.74 r0 top value=5.90k
R51 "CRCW06034K99FKEA" 0603L 2424.8,3132.77 r270 top value=4.99k
R52 "CRCW06034K99FKEA" 0603L 2925,2930 r270 top value=4.99k
R53 "CRCW060380K6FKEA" 0603 2110,968.74 r270 top value=80.6k
R54 "CRCW06032K00FKEA" 0603L 2845,2535 r270 top value=2.00k
R55 "CRCW060310K0FKEA" 0603L 2845,2640 r270 top value=10.0k
R56 "CRCW060364K9FKEA" 0603 2170,968.74 r270 top value=64.9k
R57 "CRCW06034K99FKEA" 0603L 2534.8,3222.77 r0 top value=4.99k
R58 "CRCW0603100KFKEA" 0603L 2310,968.74 r270 top value=100k
R59 "CRCW0603100KFKEA" 0603 2375,970 r270 top value=100k
R60 "CRCW06031K00FKEA" 0603L 2734.8,2822.77 r0 top value=1.00k
R61 "CRCW06030000Z0EA" 0603L 2390,1230 r180 top value=0
R62 "CRCW06032K00FKEA" 0603L 2390,1168.74 r0 top value=2.00k
R63 "CRCW06034K99FKEA" 0603L 1105,3410 r0 top value=4.99k
R64 "CRCW06034K99FKEA" 0603L 1980,3660 r180 top value=4.99k
R65 "CRCW060310K0FKEA" 0603L 2670,3488.74 r180 top value=10.0k
R66 "CRCW06034K99FKEA" 0603L 2650,3648.74 r90 top value=4.99k
R67 "CRCW060320K0FKEA" 0603L 2950,3538.74 r0 top value=20.0k
R68 "CRCW0603100KFKEA" 0603L 2910,3220 r180 top value=100k
R69 "CRCW060312K7FKEA" 0603 2910,3285 r180 top value=12.7k
R70 "CRCW06034K99FKEA" 0603L 1875,3660 r0 top value=4.99k
R71 "CRCW06034K99FKEA" 0603L 1010,3380 r90 top value=4.99k
R72 "CRCW06030000Z0EA" 0603L 2900,2950 r180 bottom value=0
R73 "CRCW06031K00FKEA" 0603L 2740,2430 r180 top value=1.00k
R74 "CRCW08052K49FKEA" 0805_HV 335,3661.67 r270 bottom value=2.49k
R75 "CRCW06034K99FKEA" 0603L 2040,3905 r0 top value=4.99k
R76 "CRCW06034K99FKEA" 0603L 1935,3905 r0 top value=4.99k
T1 "7490220122" Wurth_7490220122 560,1230 r270 top value=350uH
T2 "EP-389SG" Mentech_EP-389SG 1780,2238.74 r180 top value=100.5uH
U1 "HMHA2801A" MFP04A 3345,2230 r90 top
U2 "HMHA2801A" MFP04A 3205,2230 r90 top
U3 "HMHA2801A" MFP04A 3065,2230 r90 top
U4 "TPS2373-4RGWR" RGW0020B 3050,540 r0 top
U5 "HMHA2801A" MFP04A 2740,2228.74 r270 top
U6 "TL431AIDBVR" DBV0005A_N 2594.8,2702.77 r90 top
U7 "UCC2897ARGPR" RGP0020D 2200,1168.74 r90 top
U8 "TPS3803-01DCKR" DCK0005A_N 2905,3380 r180 top

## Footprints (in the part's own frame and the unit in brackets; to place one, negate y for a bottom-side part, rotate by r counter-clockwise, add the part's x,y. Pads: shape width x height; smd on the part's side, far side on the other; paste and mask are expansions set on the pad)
0603 [mm] "0603 from SM-752 data"
  rect 1x0.95 smd: 1(-0.8,0) 2(0.8,0)
  silkscreen extent -1.52,-0.69 1.52,0.69, body extent -0.87,-0.47 0.87,0.47, height 1
0603L [mm] "0603 from SM-752 data"
  rect 0.8x0.85 smd: 1(-0.7,0) 2(0.7,0)
  silkscreen extent -0.07,-0.33 0.07,0.33, body extent -0.87,-0.47 0.87,0.47, height 1
0805_HV [mil] "0805 with 30mil clearance between pads"
  rect 50x63 smd: 1(-40,0) 2(40,0)
  silkscreen extent -74,-40 74,40, body extent -43,-29 43,29, height 57
0805L [mm] "0805 from SM-752 data"
  rect 1.1x1.4 smd: 1(-0.75,0) 2(0.75,0)
  body extent -1.1,-0.72 1.1,0.72, height 1.45
1206_180 [mm] "1206_180"
  rect 1.1x1.6 smd: 1(-1.7,0) 2(1.7,0)
  silkscreen extent -0.9,-1 0.9,1, body extent -1.75,-0.95 1.75,0.95, height 1.8
1206L [mm] "1206 from SM-752 data"
  rect 1.1x1.75 smd: 1(-1.35,0) 2(1.35,0)
  silkscreen extent -0.4,-0.77 0.4,0.77, body extent -1.7,-0.9 1.7,0.9, height 1.35
1210_220 [mm] "1210"
  rect 1.3x2.7 smd: 1(-1.45,0) 2(1.45,0)
  silkscreen extent -2.32,-1.57 2.32,1.57, body extent -1.7,-1.35 1.7,1.35, height 2.2
1210_270 [mm] "1210"
  rect 1.3x2.7 smd: 1(-1.45,0) 2(1.45,0)
  silkscreen extent -2.32,-1.57 2.32,1.57, body extent -1.7,-1.35 1.7,1.35, height 2.7
1812 [mm]
  rect 1.6x3.4 smd: 1(-2,0) 2(2,0)
  silkscreen extent -0.8,-1.6 0.8,1.6, body extent -2.4,-1.7 2.4,1.7, height 1.35
2010 [mm] "Chip Capacitor, Body 5.08x2.54mm, IPC Medium Density"
  rect 1.6x2.7 smd: 1(-2.3,0) 2(2.3,0)
  silkscreen extent -3.42,-1.65 3.42,1.65, body extent -2.73,-1.45 2.73,1.45, height 1.66
2010L [mm]
  rect 1.2x2.7 smd: 1(-2.2,0) 2(2.2,0)
  silkscreen extent -1.2,-1.25 1.2,1.25, body extent -2.73,-1.45 2.73,1.45, height 1.66
CONN_PEC02SAAN [mm] "SULLINS"
  rrect7% 1.5x1.5 hole 1.016: 1(-1.27,0)
  round 1.5 hole 1.016: 2(1.27,0)
  silkscreen extent -2.54,-1.52 2.54,1.27, body extent -2.54,-1.27 2.54,1.27, height 8.38
DBV0005A_N [mm] "SOT23, 5-Leads, Body 2.9x1.6mm, Pitch 0.95mm, Lead Span 2.8mm, IPC Medium Density"
  rrect17% 1x0.6 smd: 1(-1.375,0.95) 2(-1.375,0) 3(-1.375,-0.95) 4(1.375,-0.95) 5(1.375,0.95)
  silkscreen extent -1.63,-1.55 0.38,1.55, body extent -1.42,-1.46 1.42,1.46, height 1.09
DCK0005A_N [mm] "SOT353, 5-Leads, Body 2x1.3mm, Pitch 0.65mm, Lead Span 2.1mm, IPC Medium Density"
  rrect25% 0.85x0.4 smd: 1(-1.125,0.65) 2(-1.125,0) 3(-1.125,-0.65) 4(1.125,-0.65) 5(1.125,0.65)
  silkscreen extent -0.15,-1.1 0.15,1.1, body extent -1.14,-1 1.14,1, height 0.95
DNH0008A_NV [mm] "8 pin VSONP, 0.65 mm pitch"
  rrect50% 0.7x0.4 smd paste-0.05 mask-0.05: 1(-1.55,0.975) 2(-1.55,0.325) 3(-1.55,-0.325) 4(-1.55,-0.975) 5(1.55,-0.975) 6(1.55,-0.325) 7(1.55,0.325) 8(1.55,0.975)
  rrect14% 0.705x1.125 on Top Paste: 9(-0.208,0.662) 9(-0.208,-0.663) 9(0.697,0.662) 9(0.697,-0.663)
  rrect6% 1.775x2.45 on Top Solder: 9(0.327,0)
  rrect4% 2.51x2.55 smd paste-1.5 mask-1.5: 9(0.645,0)
  rect 0.5x0.3 on Top Solder: 9(1.175,0.975) 9(1.175,-0.325) 9(1.175,0.325) 9(1.175,-0.975)
  silkscreen extent -1.62,-1.7 1.62,1.7, body extent -1.65,-1.65 1.65,1.66, height 0.91
DQJ0008A [mm] "SMD, 8-Leads, Body 5.75x4.9mm"
  rrect39% 0.91x0.51 smd paste-0.05 mask-0.05: 1(-2.795,1.905) 2(-2.795,0.635) 3(-2.795,-0.635) 4(-2.795,-1.905) 5(2.795,-1.905) 6(2.795,-0.635) 7(2.795,0.635) 8(2.795,1.905)
  rrect8% 1.58x1.25 on Top Paste: 9(-0.38,-1.45) 9(-0.38,0) 9(-0.38,1.45) 9(1.4,-1.45) 9(1.4,0) 9(1.4,1.45)
  rrect3% 3.48x4.47 on Top Solder: 9(0.55,0)
  rrect2% 4.49x4.57 smd paste-2.5 mask-2.5: 9(1.005,0)
  silkscreen extent -3,-2.6 3,2.6, body extent -3.13,-2.45 3.13,2.45, height 1.15
DQK0006C [mm] "WSON"
  rrect12% 0.9x0.86 on Top Paste: 0(0,0.325)
  rrect34% 0.7x0.29 on Top Paste: 0(0.095,-0.65)
  rrect33% 0.45x0.3 smd: 1(-0.975,0.65) 2(-0.975,0) 3(-0.975,-0.65) 4(0.975,-0.65) 5(0.975,0) 6(0.975,0.65)
  rrect33% 0.75x0.3 smd paste-0.15: 7(0.095,-0.65)
  rrect11% 1x0.95 smd paste-0.5: 8(0,0.325)
  silkscreen extent -1.15,-1.15 1.15,1.15, body extent -1,-1 1,1, height 0.82
LPS6235 [mm] "Coilcraft recommended land pattern.  Document 587-2, rev 10/17/08"
  rect 1.2x4.25 smd: 1(-2.7,0) 2(2.7,0)
  rect 1.68x1.6 smd rot 135: 1(-2.126,-2.151) 2(2.126,2.151)
  rect 1.68x1.6 smd rot 45: 1(-2.126,2.151) 2(2.126,-2.151)
  rect 1.125x1.2 smd: 1(-1.562,-2.7) 1(-1.562,2.7) 2(1.562,-2.7) 2(1.562,2.7)
  silkscreen extent -3.7,-3.7 3.7,3.7, body extent -3.1,-3.1 3.1,3.1, height 3.52
Mentech_EP-389SG [mm] "SMD, 10-Leads, Body 14.2x17.75mm, Pitch 2.5mm"
  rrect8% 1.3x3.4 smd: 1(-5,7.74) 2(-2.5,7.74) 3(0,7.74) 4(2.5,7.74) 5(5,7.74) 6(5,-7.74) 7(2.5,-7.74) 8(0,-7.74) 9(-2.5,-7.74) 10(-5,-7.74)
  silkscreen extent -7.6,-7.5 7.1,7.5, body extent -7.1,-8.87 7.1,8.88, height 12.7
MFP04A [mm] "FAIRCHILD optocoupler"
  rect 1.52x0.61 smd: 1(-3.175,0.635) 2(-3.175,-0.635) 3(3.175,-0.635) 4(3.175,0.635)
  silkscreen extent -2.28,-1.4 2.2,1.8, body extent -3.6,-1.34 3.6,1.34, height 2.39
MLP08S [mm] "Fairchild MLP08S recommended land pattern"
  rect 0.7x0.42 smd mask+0.051: 1(-1.4,0.975) 2(-1.4,0.325) 3(-1.4,-0.325) 4(-1.4,-0.975) 5(1.4,-0.975) 6(1.4,-0.325) 7(1.4,0.325) 8(1.4,0.975)
  Top Layer region: -0.4,-1.185 1.3,-1.185 1.3,1.185 -0.4,1.185
  silkscreen extent -1.8,-1.8 1.8,1.8, body extent -1.67,-1.67 1.67,1.67, height 0.81
MPZ2012 [mm] "TDK"
  rect 0.8x1.2 smd: 1(-0.9,0) 2(0.9,0)
  body extent -1.1,-0.72 1.1,0.72, height 1.05
MSS1278 [mm] "Coilcraft recommended land pattern.  Document 598-2 rev 04/04/13"
  rect 4x5.5 smd: 1(-4.25,0) 2(4.25,0)
  silkscreen extent -6.2,-6.2 6.2,6.2, body extent -6.15,-6.15 6.15,6.15, height 8.05
MSS5131 [mil] "Coilcraft recommended land pattern.  Document 642-2, rev 01/13/11"
  rect 20x200 smd: 1(-90,0) 2(90,0)
  Top Layer region: -31,-100 -31,-73.21 -31,-73.21 -60.67,-51.38 -77.31,-18.52 -77.36,18.32 -60.8,51.22 -31.19,73.13 -31.19,73.13 -31,73.4 -31,100 -100,100 -100,-100
  Top Layer region: 31,-100 31,-73.21 31,-73.21 60.67,-51.38 77.31,-18.52 77.36,18.32 60.8,51.22 31.19,73.13 31.19,73.13 31,73.4 31,100 100,100 100,-100
  silkscreen extent -120,-120 120,120, body extent -106,-106 106,106, height 123
POWERDI5 [mm] "Diodes Inc recommended land pattern, ap02001.pdf rev 60"
  rect 1.4x1.39 smd: 1(-1.991,0.92) 2(-1.991,-0.92)
  rect 4.86x3.36 smd: 3(1.991,0)
  silkscreen extent -1.7,-2.1 3.8,2.1, body extent -2.27,-2.02 4.33,2.03, height 1.17
RGP0020D [mm] "QFN, 20-Leads, Body 4x4mm, Pitch 0.5mm, Thermal Pad 2.7x2.7mm, TI Recommended"
  rrect42% 0.6x0.24 smd: 1(-1.9,1) 2(-1.9,0.5) 3(-1.9,0) 4(-1.9,-0.5) 5(-1.9,-1) 11(1.9,-1) 12(1.9,-0.5) 13(1.9,0) 14(1.9,0.5) 15(1.9,1)
  rrect42% 0.24x0.6 smd: 6(-1,-1.9) 7(-0.5,-1.9) 8(0,-1.9) 9(0.5,-1.9) 10(1,-1.9) 16(1,1.9) 17(0.5,1.9) 18(0,1.9) 19(-0.5,1.9) 20(-1,1.9)
  rrect8% 1.19x1.19 on Top Paste: 21(-0.695,-0.695) 21(-0.695,0.695) 21(0.695,-0.695) 21(0.695,0.695)
  rrect4% 2.7x2.7 smd paste-1.4: 21(0,0)
  silkscreen extent -2.22,-2.22 2.22,2.22, body extent -2.07,-2.07 2.07,2.07, height 1.01
RGW0020B [mm] "QFN, 20-Leads, Body 5x5mm, Pitch 0.65mm, Thermal Pad 2.2x2.2mm, TI Recommended"
  rrect32% 0.75x0.31 smd: 1(-2.325,1.3) 2(-2.325,0.65) 3(-2.325,0) 4(-2.325,-0.65) 5(-2.325,-1.3) 11(2.325,-1.3) 12(2.325,-0.65) 13(2.325,0) 14(2.325,0.65) 15(2.325,1.3)
  rrect32% 0.31x0.75 smd: 6(-1.3,-2.325) 7(-0.65,-2.325) 8(0,-2.325) 9(0.65,-2.325) 10(1.3,-2.325) 16(1.3,2.325) 17(0.65,2.325) 18(0,2.325) 19(-0.65,2.325) 20(-1.3,2.325)
  rrect10% 0.98x0.98 on Top Paste: 21(-0.59,-0.59) 21(-0.59,0.59) 21(0.59,-0.59) 21(0.59,0.59)
  rrect5% 2.2x2.2 smd paste-1.1: 21(0,0)
  silkscreen extent -2.73,-2.73 2.73,2.73, body extent -2.5,-2.5 2.5,2.5, height 0.97
SM_RADIAL_8MM [mm] "Nichicon 8x10"
  rect 3.5x2.5 smd: 1(-3.25,0) 2(3.25,0)
  silkscreen extent -4.25,-4.25 4.25,4.25, body extent -4.25,-4.25 4.25,4.25, height 10.5
SM_RADIAL_C [mm] "5 x 5.8mm:  Panasonic C"
  rect 2.8x1.6 smd: 1(-2.15,0) 2(2.15,0)
  silkscreen extent -2.75,-2.75 2.75,2.75, body extent -2.75,-2.75 2.75,2.75, height 6.1
SM_RADIAL_G [mm] "10 x 10.2mm:  Panasonic G"
  rect 4.1x2 smd: 1(-4.35,0) 2(4.35,0)
  silkscreen extent -5.35,-5.35 5.35,5.35, body extent -5.25,-5.25 5.25,5.25, height 10.5
SMB [mil] "Molded Diode, 2-Leads, Body 5.4x3.6mm, IPC Medium Density, based on OnSemi component dimensions"
  rect 85x107.99 smd: 1(-87.01,0) 2(87.01,0)
  silkscreen extent -155,-82 125,82, body extent -106,-71 106,71, height 91
SOD-123 [mm] "On Semi recommended land pattern"
  rect 0.915x1.22 smd: 1(-1.637,0) 2(1.637,0)
  silkscreen extent -2.74,-1.17 2.03,1.17, body extent -1.93,-0.9 1.93,0.9, height 1.35
SOD-523 [mm] "NXP Semiconductor recommended land pattern, nominal STEP model"
  rect 0.8x0.6 smd paste-0.05: 1(-0.55,0) 2(0.55,0)
  silkscreen extent -1.65,-0.66 1.2,0.66, body extent -0.8,-0.4 0.8,0.4, height 0.72
SOIC-8 [mm] "duplicate of SO-8.  SOIC, 8-Leads, Body 5.0x4.0mm (max), Pitch 1.27mm, IPC Medium Density"
  rrect17% 1.45x0.6 smd: 1(-2.725,1.905) 2(-2.725,0.635) 3(-2.725,-0.635) 4(-2.725,-1.905) 5(2.725,-1.905) 6(2.725,-0.635) 7(2.725,0.635) 8(2.725,1.905)
  silkscreen extent -3.5,-2.5 0.9,2.5, body extent -3,-2.45 3,2.45, height 1.63
SOT-23 [mm] "SOT23, 3-Leads, Body 2.9x1.3mm, Pitch 0.95mm, Lead Span 2.5mm, IPC Medium Density"
  rrect50% 1x0.6 smd: 1(-1.2,0.95) 2(-1.2,-0.95) 3(1.2,0)
  silkscreen extent -1.62,-1.5 0.7,1.5, body extent -1.16,-1.45 1.21,1.45, height 1
SOT-89-3 [mm] "SOT, 3-Leads, Body 4.6 x 2.6 mm, Pitch 1.5mm"
  rect 1.4x0.9 smd: 1(-1.9,1.5) 3(-1.9,-1.5)
  rect 1.8x0.9 smd: 2(-1.7,0)
  oct 3.4x1.9 smd: 4(0.9,0)
  silkscreen extent -1.3,-2.45 1.33,2.45, body extent -2.42,-2.28 1.83,2.32, height 1.62
TEC_1-406541-1 [mm] "TE Connectivity"
  round 1.4 hole 0.89: 1(3.56,-0.18) 2(2.54,1.6) 3(1.52,-0.18) 4(0.5,1.6) 5(-0.52,-0.18) 6(-1.54,1.6) 7(-2.56,-0.18) 8(-3.58,1.6)
  round 2.1 hole 1.57: 9(8.12,0.71) 10(-8.14,0.71)
  round 3.759 hole 3.251: 11(6.34,-2.72) 12(-6.36,-2.72)
  silkscreen extent -9.69,-8 9.69,8.06, body extent -9.33,-8 9.31,7.75, height 14.8
TERM_BLK_ED555-2DS [mil]
  rrect4% 100x100 hole 50: 1(0,0)
  round 100 hole 50: 2(138,0)
  silkscreen extent -93,-161 215,113, body extent -69,-150 207,106, height 323
WE-SL5 [mm] "SMD, 4-Leads, Body 8.7x10mm"
  rect 2.7x2.7 smd: 1(-3.11,3.81) 2(-3.11,-3.81) 3(3.11,-3.81) 4(3.11,3.81)
  silkscreen extent -4.35,-5 4.35,5.4, body extent -4.35,-5 4.35,5, height 6
WE-SL5_HC [mm] "SMD, 4-Leads, Body 9.5x8.3mm"
  rect 2.7x2.7 smd: 1(-3.8,3.1) 2(-3.8,-3.1) 3(3.8,-3.1) 4(3.8,3.1)
  silkscreen extent -5.2,-4.15 4.75,4.15, body extent -4.75,-4.15 4.75,4.15, height 5.31
Wurth_7490220122 [mm] "SMD, 24-Leads, Body 14.7x18.29mm"
  rect 2.29x0.76 smd: 1(-7.24,6.985) 2(-7.24,5.715) 3(-7.24,4.445) 4(-7.24,3.175) 5(-7.24,1.905) 6(-7.24,0.635) 7(-7.24,-0.635) 8(-7.24,-1.905) 9(-7.24,-3.175) 10(-7.24,-4.445) 11(-7.24,-5.715) 12(-7.24,-6.985) 13(7.24,-6.985) 14(7.24,-5.715) 15(7.24,-4.445) 16(7.24,-3.175) 17(7.24,-1.905) 18(7.24,-0.635) 19(7.24,0.635) 20(7.24,1.905) 21(7.24,3.175) 22(7.24,4.445) 23(7.24,5.715) 24(7.24,6.985)
  silkscreen extent -7.7,-9.15 7.35,9.15, body extent -7.35,-9.15 7.35,9.15, height 8.81

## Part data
C1 C6: "CAP, CERM, 1000 pF, 2000 V, +/- 10%, X7R, 1812", Cap_Case=1812, Manufacturer=MuRata, TempCo=X7R, Tolerance_%=10, Value1=Unknown, Value2=2000V, ValueDisplayed=1000pF
C2 C3 C4 C5: "CAP, CERM, 0.01 µF, 100 V, +/- 10%, X7R, 0603", Cap_Case=0603, Manufacturer=MuRata, Supplier Part Number 1=GRM188R72A103KA01D-ND, TempCo=X7R, Tolerance_%=10, Value1=Unknown, Value2=100V, ValueDisplayed=0.01µF
C7 C8 C42 C43: library part CMP-0007467-2, "CAP, CERM, 1000 pF, 100 V, +/- 10%, X7R, 0603", Cap_Case=0603, Manufacturer=MuRata, Supplier Part Number 1=490-1472-1-ND, TempCo=X7R, Tolerance_%=10%, Value1=Unknown, Value2=100V, ValueDisplayed=1000pF
C9 C17: "CAP, AL, 47 µF, 80 V, +/- 20%, 0.7 ohm, AEC-Q200 Grade 2, SMD", Cap_Case=G, Manufacturer=Panasonic, Supplier Part Number 1=PCE3831CT-ND, Tolerance_%=20, Value1="0.7 ohm", Value2=80V, ValueDisplayed=47µF
C10: "CAP, CERM, 0.1 µF, 100 V, +/- 10%, X7R, 0805", Cap_Case=0805, Manufacturer=TDK, Supplier Part Number 1=445-1418-1-ND, TempCo=X7R, Tolerance_%=10, Value1="0.020726 ohm", Value2=100V, ValueDisplayed=0.1µF
C11 C12 C13 C14: "CAP, CERM, 330 pF, 50 V, +/- 5%, C0G/NP0, 0603", Cap_Case=0603, Manufacturer=MuRata, Supplier Part Number 1=490-1439-1-ND, TempCo=C0G/NP0, Tolerance_%=5, Value1=Unknown, Value2=50V, ValueDisplayed=330pF
C15 C30 C39: "CAP, CERM, 0.1 µF, 50 V, +/- 10%, X7R, 0603", Cap_Case=0603, Manufacturer=TDK, Supplier Part Number 1=445-1314-1-ND, TempCo=X7R, Tolerance_%=10, Value1="0.0296 ohm", Value2=50V, ValueDisplayed=0.1µF
C16 C29: "CAP, CERM, 2200 pF, 2000 V,+/- 10%, X7R, 1812", Cap_Case=1812, Manufacturer=TDK, Supplier Part Number 1=445-2389-1-ND, TempCo=X7R, Tolerance_%=10, Value2=2000V, ValueDisplayed=2200pF
C18 C37: "CAP, Aluminum Polymer, 47 µF, 20 V,+/- 20%, 0.045 ohm, 8x10 SMD", Cap_Case=8.3x8.3x6.9, Manufacturer=Panasonic, Tolerance_%=20, Value1="0.045 ohm", Value2=20V, ValueDisplayed=47µF
C19 C20: "CAP, CERM, 2.2 µF, 100 V, +/- 10%, X7R, 1210", Cap_Case=1210, Manufacturer=MuRata, Supplier Part Number 1=490-3385-1-ND, TempCo=X7R, Tolerance_%=10, Value1="0.007 ohm", Value2=100V, ValueDisplayed=2.2µF
C21 C26 C33: "CAP, CERM, 100 pF, 50 V,+/- 5%, C0G/NP0, 0603", Cap_Case=0603, Manufacturer=TDK, Supplier Part Number 1=445-173611-1-ND, TempCo=C0G/NP0, Tolerance_%=5, Value2=50V, ValueDisplayed=100pF
C22 C23 C40: "CAP, CERM, 10 µF, 25 V,+/- 10%, X7R, 1210", Cap_Case=1210, Manufacturer="Wurth Elektronik", Supplier Part Number 1=732-7729-1-ND, TempCo=X7R, Tolerance_%=10, Value2=25V, ValueDisplayed=10µF
C24: "CAP, CERM, 2200 pF, 50 V, +/- 10%, X7R, 0603", Cap_Case=0603, Manufacturer=MuRata, Supplier Part Number 1=490-1500-1-ND, TempCo=X7R, Tolerance_%=10, Value1=Unknown, Value2=50V, ValueDisplayed=2200pF
C25: library part CMP-0008975-2, "CAP, CERM, 0.047 uF, 250 V, +/- 10%, X7R, 1206", Cap_Case=1206, Manufacturer=MuRata, Supplier Part Number 1=490-3538-1-ND, TempCo=X7R, Tolerance_%=10%, Value1=Unknown, Value2=250V, ValueDisplayed=0.047uF
C27 C31 C36 C38 C41: "CAP, CERM, 1 µF, 25 V, +/- 10%, X7R, 0805", Cap_Case=0805, Manufacturer=MuRata, Supplier Part Number 1=GRM21BR71E105KA99L-ND, TempCo=X7R, Tolerance_%=10, Value1=Unknown, Value2=25V, ValueDisplayed=1µF
C28: "CAP, CERM, 47 pF, 50 V, +/- 5%, C0G/NP0, 0603", Cap_Case=0603, Manufacturer=MuRata, Supplier Part Number 1=490-1419-1-ND, TempCo=C0G/NP0, Tolerance_%=5, Value1=Unknown, Value2=50V, ValueDisplayed=47pF
C32 C34: "CAP, CERM, 0.022 µF, 50 V, +/- 10%, X7R, 0603", Cap_Case=0603, Manufacturer=MuRata, Supplier Part Number 1=490-1517-1-ND, TempCo=X7R, Tolerance_%=10, Value1=Unknown, Value2=50V, ValueDisplayed=0.022µF
C35: "CAP, CERM, 1000 pF, 50 V,+/- 10%, X7R, 0603", Cap_Case=0603, Manufacturer=MuRata, Supplier Part Number 1=490-1494-1-ND, TempCo=X7R, Tolerance_%=10, Value2=50V, ValueDisplayed=1000pF
C44: "CAP, CERM, 0.01 µF, 50 V, +/- 10%, X7R, 0603", Cap_Case=0603, Manufacturer=TDK, Supplier Part Number 1=445-1311-1-ND, TempCo=X7R, Tolerance_%=10, Value1="0.0539 ohm", Value2=50V, ValueDisplayed=0.01µF
C45: library part CMP-0010713-1, "CAP, AL, 22 uF, 25 V, +/- 20%, 0.7 ohm, AEC-Q200 Grade 2, SMD", Cap_Case=C, Manufacturer=Panasonic, Supplier Part Number 1=PCE3799CT-ND, Tolerance_%=20%, Value1="0.7 ohm", Value2=25V, ValueDisplayed=22uF
D1 D2 D3 D4: "Diode, Schottky, 100V, 2A, SMB", Manufacturer="Diodes Inc.", Supplier Part Number 1=B2100-FDICT-ND, Value1=2A, Value2=0.79V
D5 D6: "Diode, TVS, Uni, 58V, 600W, SMB", Manufacturer="Diodes Inc.", Power_W=5, Supplier Part Number 1=SMBJ58A-FDICT-ND, Value1=5W
D7 D8 D9 D11 D13 D14 D17 D19: "Diode, Switching, 100 V, 0.2 A, SOD-123", Manufacturer="ON Semiconductor", Supplier Part Number 1=MMSD4148T1GOSCT-ND, Value1=0.2A, Value2=1V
